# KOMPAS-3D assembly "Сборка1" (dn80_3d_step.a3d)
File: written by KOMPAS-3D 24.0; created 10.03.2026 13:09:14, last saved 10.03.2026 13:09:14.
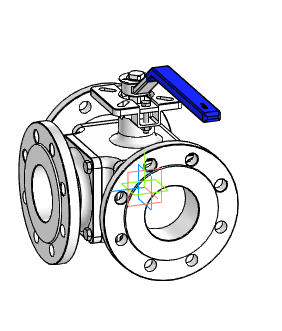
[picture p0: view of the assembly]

Document properties: Автор: R2D2; Полное имя файла: E:\Работа\Зайцев\BV3232P(4pc)-FP-3WL-F-ISO-H Кран шаровой DN.ru Ду15-100 Ру16\DN80\исходные материалы\dn80_3d_step.a3d

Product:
- Component [detail]: Деталь  | qty 1  | Автор: R2D2; source file: Деталь Деталь.m3d
- Component [detail]: Деталь1  | qty 1  | Автор: R2D2; source file: Деталь1 Деталь1.m3d
- Component [detail]: AS 1110 - M8 x 40  | qty 1  | Автор: R2D2; source file: AS 1110 - M8 x 40 AS 1110 - M8 x 40.m3d
- Component [detail]: AS 1110 - M8 x 40  | qty 1  | Комментарий: Болты и винты   шестигранные точные   метрические ISO; Автор: R2D2; additional columns: Сталь, мягкая; source file: AS 1110 - M8 x 40 AS 1110 - M8 x 40.m3d
- Component [detail]: ANSI B18.2.4.2M - M8x1,25 - 13  | designation ANSI B18.2.4.2M - M8x1,25  | qty 1  | Автор: R2D2; source file: ANSI B18.2.4.2M - M8x1,25 ANSI B18.2.4.2M - M8x1,25 - 13.m3d
- Component [detail]: ANSI B18.2.4.2M - M8x1,25 - 13  | designation ANSI B18.2.4.2M - M8x1,25  | qty 1  | Комментарий: Типы метрических   шестигранных гаек   2; Автор: R2D2; additional columns: Сталь, мягкая; source file: ANSI B18.2.4.2M - M8x1,25 ANSI B18.2.4.2M - M8x1,25 - 13.m3d
- Component [detail]: AS 1110 - M10 x 16  | qty 1  | Автор: R2D2; source file: AS 1110 - M10 x 16 AS 1110 - M10 x 16.m3d
- Component [detail]: AS 1110 - M10 x 16  | qty 11  | Комментарий: Болты и винты   шестигранные точные   метрические ISO; Автор: R2D2; additional columns: Сталь, мягкая; source file: AS 1110 - M10 x 16 AS 1110 - M10 x 16.m3d
- Part/product: Сборка1

Referenced files in E:\Работа\Зайцев\BV3232P(4pc)-FP-3WL-F-ISO-H Кран шаровой DN.ru Ду15-100 Ру16\DN80\исходные материалы\: Деталь Деталь.m3d, Деталь1 Деталь1.m3d, AS 1110 - M8 x 40 AS 1110 - M8 x 40.m3d, ANSI B18.2.4.2M - M8x1,25 ANSI B18.2.4.2M - M8x1,25 - 13.m3d, AS 1110 - M10 x 16 AS 1110 - M10 x 16.m3d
